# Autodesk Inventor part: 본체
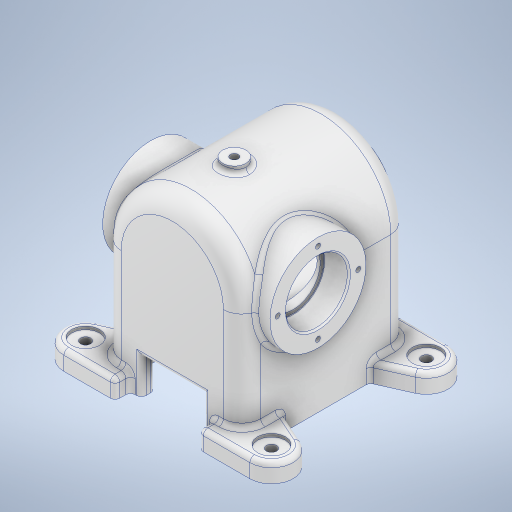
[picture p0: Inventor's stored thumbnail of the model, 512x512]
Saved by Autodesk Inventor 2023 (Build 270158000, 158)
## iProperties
Created: 2024-09
Part Number: 본체
Material: 알루미늄 6061
Document SubType Name: Modeling
Designer: home
Density: 2.7 g/cm^3
Appearance: 알루미늄 - 평지
Mass: 1473.92 g
Surface Area: 1119.68 cm^2
Volume: 545.898 cm^3
Author: home
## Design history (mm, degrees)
sketch "스케치1" dims "d2" = 90
  geometry: L1 (-45, 76)-(45, 76); L2 (45, 76)-(45, 0); L3 (45, 0)-(-45, 0); L4 (-45, 0)-(-45, 76); 6 further points
  constraints: 8 end point, 2 midpoint, 2 parallel, 1 coincident, 1 horizontal, 1 perpendicular, 3 other
  dimensions: "d0" = 90 distance of L2.end L3.end; "d7" = 121 distance from line of L3 point (0, 121); "d8" = 76 distance of L3.end L1.start
extrude "돌출1" new body sketch "스케치1" stored distance "d3" = 108; taper "d4" = 0 deg
sketch "스케치2"
  geometry: L1 (-45, 0)-(45, 0) reference; C1 r 28.5 at (0, 76); 1 further point
  constraints: 1 centre point
  dimensions: "d5" = 57 diameter of C1; "d6" = 76 distance from line of L1 C1.centre
extrude "돌출2" join sketch "스케치2" distance "d9" = 6; taper "d10" = 0 deg
node "작업 평면1"
sketch "스케치4"
  geometry: C1 r 16.5 at (0, 0); 1 further point
  constraints: 1 centre point, 1 vertical alignment
  dimensions: "d16" = 33 diameter of C1
extrude "돌출3" cut sketch "스케치4" distance "d17" = 15; taper "d18" = 0 deg
sketch "스케치6"
  geometry: L1 (27, 64)-(60, 64); L2 (65.693, 37.21)-(45, 28); L3 (45, 54)-(-45, 54) reference; L4 (45, 54)-(45, -54) reference; L5 (27, 64)-(27, 54); L6 (0, 54)-(0, 0); L7 (45, -54)-(45, 54) reference; A1 r 14 centre (60, 50) between (60, 64) and (65.693, 37.21); 3 further points
  constraints: 8 end point, 2 point on circle, 2 tangent, 2 vertical, 1 centre point, 1 coincident, 1 horizontal alignment, 1 midpoint, 1 vertical alignment
  dimensions: "d23" = 36 distance from line of L1 point (45, 28); "d25" = 18 distance from line of L4 L1.start; "d26" = 60 distance from line of L6 A1.centre; "d27" = 50 vertical distance of A1.centre L6.end; "d28" = 14 distance from line of L1 A1.centre
extrude "돌출5" join sketch "스케치6" distance "d29" = 12; taper "d30" = 0 deg
sketch "스케치7"
  geometry: L1 (-60, -64)-(-27, -64) reference; L2 (0, 66.899)-(0, -57.494); 2 further points
  constraints: 2 end point, 1 vertical
  dimensions: "d32" = 14 distance from line of L1 point (-60, -50); "d33" = 60 horizontal distance of point (-60, -50) L2.end
hole "구멍1" sketch "스케치7" at (-60, -50) diameter "d34" = 6.6; stored, may be unused: countersink angle "d38" = 90 deg, drill point angle "d40" = 0 deg; dims "d35" = 6, "d36" = 18, "d37" = 2, "d39" = 12
sketch "스케치8"
  geometry: L1 (-20, 23)-(20, 23); L2 (20, 23)-(20, 0); L3 (20, 0)-(-20, 0); L4 (-20, 0)-(-20, 23); L5 (-27, 0)-(27, 0) reference; 2 further points
  constraints: 8 end point, 2 midpoint, 2 parallel, 1 horizontal, 1 perpendicular
  dimensions: "d41" = 40 distance of L2.end L3.end; "d42" = 23 distance of L3.end L1.start
extrude "돌출6" cut sketch "스케치8" extent not by distance; stored distance "d43" = 0; taper "d44" = 0 deg
sketch "스케치9"
  geometry: L1 (-63, -19)-(9, -19); L2 (9, -19)-(9, -109); L3 (9, -109)-(-63, -109); L4 (-63, -109)-(-63, -19); L5 (-63, -19)-(9, -109); L6 (9, -19)-(-63, -109); L7 (18, -92)-(18, -36) reference; L8 (-55.5, -124)-(1.5, -124) reference; L9 (0, -118)-(-7, -118) reference; 1 further point
  constraints: 12 end point, 2 midpoint, 2 parallel, 1 horizontal, 1 perpendicular
  dimensions: "d45" = 9 distance between parallel lines of L7 L2; "d47" = 9 distance between parallel lines of L9 L3
extrude "돌출7" cut sketch "스케치9" distance "d48" = 31; taper "d49" = 0 deg
node "작업 평면2"
sketch "스케치10"
  geometry: L1 (-28.5, -60)-(28.5, -60) reference; C1 r 7.5 at (0, 14); 1 further point
  constraints: 1 centre point, 1 vertical alignment
  dimensions: "d51" = 74 distance from line of L1 C1.centre; "d52" = 15 diameter of C1
extrude "돌출8" join sketch "스케치10" distance "d53" = 7; taper "d54" = 0 deg
node "작업 평면3"
sketch "스케치11"
  geometry: 2 further points
hole "구멍2" sketch "스케치11" at (0, 0) diameter "d56" = 5.1881; stored, may be unused: countersink angle "d60" = 90 deg, drill point angle "d62" = 0 deg; dims "d57" = 12, "d58" = 18, "d59" = 2, "d61" = 8
fillet "모깎기2" dims "d63" = 3
sketch "스케치12" dims "d64" = 46
  geometry: 3 further points
  constraints: 1 vertical alignment, 2 other
hole "구멍3" sketch "스케치12" at (0, 23) diameter "d65" = 3.242; stored, may be unused: countersink angle "d69" = 90 deg, drill point angle "d71" = 118 deg; dims "d66" = 8, "d67" = 4, "d68" = 2, "d70" = 10
fillet "모깎기3" dims "d75" = 12
fillet "모깎기4" dims "d76" = 3
fillet "모깎기5" dims "d77" = 3
fillet "모깎기6" dims "d78" = 3
fillet "모깎기7" dims "d79" = 3
node "작업 평면4"
sketch "스케치13"
  geometry: L1 (54, -31)-(-54, -31); L2 (-54, -31)-(-54, 31); L3 (-54, 31)-(54, 31); L4 (54, 31)-(54, -31); L5 (54, -31)-(-54, 31); L6 (-54, -31)-(54, 31); L7 (-54, 0)-(54, 0); L8 (-60, -76)-(-74, -76) reference; 4 further points
  constraints: 14 end point, 5 midpoint, 2 parallel, 1 horizontal, 1 perpendicular, 1 vertical alignment
  dimensions: "d81" = 62 diameter of L3 L7; "d82" = 76 distance between parallel lines of L8 L7; "d83" = 108 distance of L2.end L3.end
revolve "회전2" sketch "스케치13" stored, may be unused: angle "d84" = 90 deg
sketch "스케치14"
  geometry: C1 r 20 at (0, 0); 1 further point
  constraints: 1 centre point
  dimensions: "d85" = 40 diameter of C1
extrude "돌출9" cut sketch "스케치14" distance "d86" = 16; taper "d87" = 0 deg
sketch "스케치15"
  geometry: C1 r 17.5 at (0, 0); 1 further point
  constraints: 1 centre point
  dimensions: "d88" = 35 diameter of C1
extrude "돌출10" cut sketch "스케치15" extent not by distance; stored distance "d89" = 0; taper "d90" = 0 deg
sketch "스케치16"
  geometry: C1 r 20 at (0, 0); 1 further point
  constraints: 1 centre point
  dimensions: "d91" = 40 diameter of C1
extrude "돌출11" cut sketch "스케치16" distance "d92" = 16; taper "d93" = 0 deg
fillet "모깎기8" dims "d94" = 0.3
sketch "스케치17" dims "d95" = 52
  geometry: 3 further points
  constraints: 1 vertical alignment, 2 other
hole "구멍4" sketch "스케치17" at (0, 26) diameter "d96" = 3.242; stored, may be unused: countersink angle "d100" = 90 deg, drill point angle "d102" = 118 deg; dims "d97" = 8, "d98" = 4, "d99" = 2, "d101" = 10
fillet "모깎기9" dims "d106" = 3
chamfer "모따기1" distance "d107" = 1; stored, may be unused: second distance "d108" = 2, angle "d109" = 45 deg
chamfer "모따기2" distance "d110" = 1; stored, may be unused: second distance "d111" = 2, angle "d112" = 45 deg
chamfer "모따기3" distance "d113" = 1; stored, may be unused: second distance "d114" = 2, angle "d115" = 45 deg
sketch "스케치18"
  geometry: L1 (-60, 0)-(-30, 0) reference; 2 further points
  constraints: 1 vertical alignment, 1 other
  dimensions: "d116" = 35 distance from line of L1 point (0, 35)
feature "엠보싱1" sketch "스케치18" dims "d117" = 0.5, "d118" = 0
sketch "스케치19"
  geometry: C1 r 36 at (0, 0); 1 further point
  constraints: 1 centre point
  dimensions: "d119" = 72 diameter of C1
extrude "돌출12" cut sketch "스케치19" distance "d120" = 90; taper "d121" = 0 deg
fillet "모깎기10" dims "d122" = 3
feature "̐耀̒耀̔耀̖耀̘耀̚耀̜耀̞耀" dims "d0" = 90, "d2" = 90, "d3" = 108, "d4" = 0, "d5" = 57, "d6" = 76, "d7" = 121, "d8" = 76, "d9" = 6, "d10" = 0, "d11" = -74, "d16" = 33, "d17" = 15, "d18" = 0, "d23" = 36, "d25" = 18, "d26" = 60, "d27" = 50, "d28" = 14, "d29" = 12, "d30" = 0, "d32" = 14, "d33" = 60, "d34" = 6.6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
feature "ԛ耀ԝ耀ԟ耀ԡ耀ԣ耀ԥ耀ԧ耀ԩ耀" dims "d0" = 90, "d2" = 90, "d3" = 108, "d4" = 0, "d5" = 57, "d6" = 76, "d7" = 121, "d8" = 76, "d9" = 6, "d10" = 0, "d11" = -74, "d16" = 33, "d17" = 15, "d18" = 0, "d23" = 36, "d25" = 18, "d26" = 60, "d27" = 50, "d28" = 14, "d29" = 12, "d30" = 0, "d32" = 14, "d33" = 60, "d34" = 6.6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
node "솔리드1"
mirror "미러1"
mirror "미러2"
mirror "미러3"
pattern_circular "원형 패턴1" dims angle "d73" = 360 deg
pattern_circular "원형 패턴2" dims angle "d104" = 360 deg
mirror "미러4"
feature "A9D066F2-1C7D-4E18-AEED-F7BC21143FA4" dims "d34" = 6.6, "d35" = 6, "d36" = 18, "d37" = 2, "d38" = 90 deg, "d39" = 12, "d40" = 0
